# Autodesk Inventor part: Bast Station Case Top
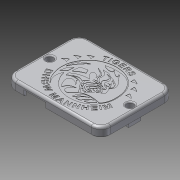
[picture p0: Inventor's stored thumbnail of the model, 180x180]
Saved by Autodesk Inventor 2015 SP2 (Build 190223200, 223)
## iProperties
Created: 2014-11
Part Number: Bast Station Case Top
Material: PC/ABS-Kunststoff
Document SubType Name: Modeling
Designer: rYan
Mass: 20.7912 g
Surface Area: 144.823 cm^2
Volume: 13.9258 cm^3
Density: 1.493 g/cm^3
Appearance: Glatt - weiß
Author: rYan
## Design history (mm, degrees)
node "Blöcke"
  sketch "Logo"
    geometry: L1 (132.873, 379.318)-(132.65, 379.619); L2 (132.65, 379.619)-(131.014, 379.945); L3 (131.014, 379.945)-(131.014, 379.945); L4 (129.973, 378.966)-(129.973, 378.966); L5 (129.973, 378.966)-(133.096, 379.016); L6 (133.096, 379.016)-(132.873, 379.318); L7 (131.014, 379.945)-(129.973, 378.966); L8 (131.956, 378.489)-(131.683, 378.414); L9 (131.683, 378.414)-(131.336, 377.836); L10 (131.336, 377.836)-(132.154, 377.736); L11 (132.154, 377.736)-(132.972, 377.635); L12 (132.972, 377.635)-(133.269, 377.309); L13 (133.269, 377.309)-(133.492, 377.409); L14 (133.492, 377.409)-(133.715, 377.51); L15 (133.715, 377.51)-(133.52, 377.541); L16 (133.52, 377.541)-(133.492, 378.112); L17 (133.492, 378.112)-(133.443, 379.117); L18 (133.443, 379.117)-(132.228, 378.564); L19 (132.228, 378.564)-(131.956, 378.489); L20 (129.066, 372.599)-(129.286, 373.295); L21 (129.286, 373.295)-(130.826, 372.487); L22 (130.826, 372.487)-(131.87, 372.626); L23 (131.87, 372.626)-(132.915, 372.766); L24 (132.915, 372.766)-(130.496, 373.657); L25 (130.496, 373.657)-(128.984, 373.295); L26 (128.984, 373.295)-(127.472, 372.933); L27 (127.472, 372.933)-(126.043, 373.378); L28 (126.043, 373.378)-(127.197, 374.994); L29 (127.197, 374.994)-(128.352, 376.609); L30 (128.352, 376.609)-(130.853, 378.28); L31 (130.853, 378.28)-(130.853, 378.28); L32 (128.819, 378.307)-(128.819, 378.307); L33 (128.819, 378.307)-(125.96, 375.857); L34 (125.96, 375.857)-(125.136, 375.634); L35 (125.136, 375.634)-(126.125, 373.796); L36 (126.125, 373.796)-(125.533, 372.884); L37 (125.533, 372.884)-(126.318, 372.487); L38 (126.318, 372.487)-(127.197, 372.042); L39 (127.197, 372.042)-(129.369, 371.039); L40 (129.369, 371.039)-(130.826, 371.234); L41 (130.826, 371.234)-(131.046, 371.624); L42 (131.046, 371.624)-(131.376, 372.097); L43 (131.376, 372.097)-(131.376, 372.097); L44 (131.376, 372.097)-(131.376, 372.097); L45 (131.376, 372.097)-(128.847, 371.902); L46 (128.847, 371.902)-(129.066, 372.599); L47 (130.853, 378.28)-(128.819, 378.307); L48 (124.888, 373.211)-(124.806, 373.657); L49 (124.806, 373.657)-(123.929, 374.483); L50 (123.929, 374.483)-(123.734, 374.186); L51 (123.734, 374.186)-(123.349, 373.601); L52 (123.349, 373.601)-(122.002, 375.105); L53 (122.002, 375.105)-(122.002, 375.105); L54 (122.002, 375.105)-(122.002, 375.105); L55 (122.002, 375.105)-(123.541, 373.072); L56 (123.541, 373.072)-(123.816, 372.766); L57 (123.816, 372.766)-(124.503, 372.738); L58 (124.503, 372.738)-(124.971, 372.766); L59 (124.971, 372.766)-(124.888, 373.211); L60 (130.228, 362.052)-(131.209, 362.075); L61 (131.209, 362.075)-(132.085, 362.167); L62 (132.085, 362.167)-(133.407, 362.421); L63 (133.407, 362.421)-(133.726, 362.482); L64 (133.726, 362.482)-(134.413, 365.932)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; 10 further points
    constraints: 358 end point, 8 point on line, 1 coincident, 835 other
  sketch "TigersLogo"
    geometry: L1 (136.84, 401.699)-(136.765, 401.634); L2 (136.951, 401.726)-(136.84, 401.699); L3 (136.765, 401.634)-(136.725, 401.531); L4 (136.725, 401.531)-(136.688, 401.438); L5 (136.688, 401.438)-(136.698, 401.342); L6 (136.698, 401.342)-(136.753, 401.244); L7 (136.753, 401.244)-(136.824, 401.119); L8 (136.824, 401.119)-(137.041, 400.933); L9 (137.041, 400.933)-(137.404, 400.686); L10 (137.404, 400.686)-(137.767, 400.439); L11 (137.767, 400.439)-(138.025, 400.23); L12 (138.025, 400.23)-(138.178, 400.057); L13 (138.178, 400.057)-(138.331, 399.885); L14 (138.331, 399.885)-(138.429, 399.693); L15 (138.429, 399.693)-(138.47, 399.481); L16 (138.47, 399.481)-(138.512, 399.269); L17 (138.512, 399.269)-(138.485, 399.038); L18 (138.485, 399.038)-(138.387, 398.787); L19 (138.387, 398.787)-(138.299, 398.561); L20 (138.299, 398.561)-(138.152, 398.374); L21 (138.152, 398.374)-(137.946, 398.226); L22 (137.946, 398.226)-(137.74, 398.078); L23 (137.74, 398.078)-(137.5, 398.002); L24 (137.5, 398.002)-(137.226, 397.998); L25 (137.226, 397.998)-(136.952, 397.994); L26 (136.952, 397.994)-(136.639, 398.06); L27 (136.639, 398.06)-(136.286, 398.197); L28 (136.286, 398.197)-(135.773, 398.397); L29 (135.773, 398.397)-(135.424, 398.666); L30 (135.424, 398.666)-(135.238, 399.004); L31 (135.238, 399.004)-(135.053, 399.342); L32 (135.053, 399.342)-(135.02, 399.743); L33 (135.02, 399.743)-(135.138, 400.206); L34 (138.922, 400.506)-(138.088, 400.79); L35 (116.631, 365.972)-(116.631, 365.972); L36 (116.631, 365.972)-(116.205, 368.113); L37 (116.205, 368.113)-(116.631, 368.745); L38 (116.631, 368.745)-(117.087, 369.423); L39 (117.087, 369.423)-(119.429, 368.776); L40 (119.429, 368.776)-(119.429, 368.776); L41 (119.429, 368.776)-(119.429, 368.776); L42 (119.429, 368.776)-(118.517, 368.591); L43 (118.517, 368.591)-(117.757, 368.036); L44 (117.757, 368.036)-(117.027, 367.504); L45 (117.027, 367.504)-(116.631, 365.972); L46 (116.631, 365.972)-(116.631, 365.972); L47 (140.827, 377.298)-(141.094, 377.264); L48 (141.094, 377.264)-(142.968, 375.535); L49 (142.968, 375.535)-(143.203, 375.162); L50 (143.203, 375.162)-(143.437, 374.789); L51 (143.437, 374.789)-(143.336, 374.586); L52 (143.336, 374.586)-(143.035, 374.958); L53 (143.035, 374.958)-(142.734, 375.331); L54 (142.734, 375.331)-(140.659, 376.993); L55 (140.659, 376.993)-(140.659, 376.993); L56 (140.659, 376.993)-(140.659, 376.993); L57 (140.659, 376.993)-(140.559, 377.332); L58 (140.559, 377.332)-(140.827, 377.298); L59 (144.039, 377.332)-(143.002, 377.365); L60 (143.002, 377.365)-(140.091, 378.281); L61 (140.091, 378.281)-(140.091, 378.281); L62 (140.091, 378.281)-(140.091, 378.281); L63 (140.091, 378.281)-(141.621, 378.209); L64 (141.621, 378.209)-(142.782, 377.954)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; 1 further point
    constraints: 358 end point, 825 other
sketch "Skizze1"
  geometry: L1 (-37, 28)-(37, 28); L2 (37, 28)-(37, -28); L3 (37, -28)-(-37, -28); L4 (-37, -28)-(-37, 28); L5 (0, 39.2)-(0, -39.2) reference; L6 (-51.8, 0)-(51.8, 0) reference; 1 further point
  constraints: 8 end point, 2 parallel, 1 horizontal, 1 perpendicular, 2 other
  dimensions: "d0" = 56 distance of L3.end L1.start; "d2" = 74 distance of L1.start L1.end
extrude "Extrusion1" new body sketch "Skizze1" distance "d3" = 5; taper "d4" = 0 deg
feature "Wandstärke1" dims "d5" = 2
fillet "Rundung1" dims "d6" = 6, "d7" = 8
sketch "Skizze2"
  geometry: L1 (39, 8.4)-(39, -1.4) reference; L2 (70, 0)-(8, 0) reference; L3 (8, 7)-(70, 7) reference; L4 (32.6, 0)-(14.6, 0); L5 (14.6, 0)-(14.6, 4); L6 (14.6, 4)-(32.6, 4); L7 (32.6, 4)-(32.6, 0); L8 (70, 7)-(70, 0) reference; L9 (8, 0)-(8, 7) reference; 1 further point
  constraints: 8 end point, 2 parallel, 1 horizontal, 1 perpendicular, 1 point on line
  dimensions: "d8" = 6.4 distance between parallel lines of L1 L7; "d9" = 18 distance of L5.end L6.end; "d10" = 4 distance of L4.end L5.end
extrude "Extrusion2" cut sketch "Skizze2" distance "d11" = 3; taper "d12" = 0 deg
sketch "Skizze3"
  geometry: L1 (8, 0)-(70, 0) reference; L2 (70, -7)-(8, -7) reference; L3 (39, 1.4)-(39, -8.4) reference; L4 (16.5, 0)-(60.5, 0); L5 (60.5, 0)-(60.5, -2); L6 (60.5, -2)-(16.5, -2); L7 (16.5, -2)-(16.5, 0); L8 (70, 0)-(70, -7) reference; L9 (8, -7)-(8, 0) reference; 1 further point
  constraints: 8 end point, 2 parallel, 1 horizontal, 1 perpendicular, 1 point on line
  dimensions: "d13" = 2 distance of L6.end L4.start; "d15" = 44 distance of L5.end L6.end; "d16" = 22.5 distance between parallel lines of L7 L3
extrude "Extrusion3" cut sketch "Skizze3" distance "d17" = 3; taper "d18" = 0 deg
feature "Lippe1" dims "d19" = 1, "d20" = 1.2, "d21" = 0, "d22" = 0, "d23" = 10 deg, "d24" = 0
sketch "Skizze4"
  geometry: L1 (6, 0)-(68, 0) reference; L2 (0, -50)-(0, -6) reference; L3 (68, -56)-(6, -56) reference; L4 (74, -6)-(74, -50) reference; L5 (74, -23)-(66, -23); L6 (66, -23)-(66, -33); L7 (66, -33)-(74, -33); L8 (74, -33)-(74, -23); L9 (0, -23)-(8, -23); L10 (8, -23)-(8, -33); L11 (8, -33)-(0, -33); L12 (0, -33)-(0, -23); L13 (-17.6, -28)-(91.6, -28) reference; L14 (37, -70)-(37, 14) reference; A1 r 6 centre (6, -50) between (0, -50) and (6, -56) reference; A2 r 6 centre (68, -50) between (68, -56) and (74, -50) reference; A3 r 6 centre (68, -6) between (74, -6) and (68, 0) reference; A4 r 6 centre (6, -6) between (6, 0) and (0, -6) reference; 1 further point
  constraints: 16 end point, 4 parallel, 2 horizontal, 2 perpendicular, 2 point on line, 4 other
  dimensions: "d25" = 10 distance of L5.end L6.end; "d27" = 8 distance of L6.end L7.end
extrude "Extrusion4" join sketch "Skizze4" distance "d28" = 10; taper "d29" = 0 deg
sketch "Skizze5"
  geometry: L1 (-37, 5)-(-29, 5) reference; L2 (-29, 5)-(-29, -5) reference; L3 (-29, -5)-(-37, -5) reference; L4 (-37, -5)-(-37, 5) reference; L5 (37, 5)-(37, -5) reference; L6 (37, -5)-(29, -5) reference; L7 (29, -5)-(29, 5) reference; L8 (29, 5)-(37, 5) reference; L9 (-33, 5)-(-33, -5); L10 (33, 5)-(33, -5); C1 r 3 at (-33, 0); C2 r 3 at (33, 0); 1 further point
  constraints: 6 midpoint, 4 end point, 2 centre point
  dimensions: "d30" = 6 diameter of C1; "d31" = 6 diameter of C2
extrude "Extrusion5" cut sketch "Skizze5" distance "d32" = 10; taper "d33" = 0 deg
sketch "Skizze6"
  geometry: C1 r 3 at (0, 0) reference; C2 r 3 at (66, 0) reference; 3 further points
  constraints: 2 coincident
hole "Bohrung1" sketch "Skizze6" at (0, 0), (66, 0) diameter "d34" = 3.2; stored, may be unused: countersink angle "d38" = 90 deg, drill point angle "d40" = 118 deg; dims "d35" = 6, "d36" = 4, "d37" = 2, "d39" = 8
fillet "Rundung2" dims "d41" = 2
feature "Flächenverjüngung1" dims angle "d42" = 5 deg
feature "Flächenverjüngung2" dims angle "d43" = 5 deg
fillet "Rundung3" dims "d44" = 1
sketch "Skizze7"
  geometry: L1 (0, 56)-(62, 56) reference; L2 (9.5, 56)-(0, 56) reference; L3 (9.5, 56)-(53.5, 56) reference; L4 (62, 56)-(53.5, 56) reference; L5 (-8, 4)-(-8, 48) reference; L6 (-8, 48)-(-8, 4) reference; L7 (11, 42)-(51, 42); L8 (51, 42)-(51, 37); L9 (51, 37)-(11, 37); L10 (11, 37)-(11, 42); L11 (31, -16)-(31, 68) reference; 1 further point
  constraints: 8 end point, 2 parallel, 1 horizontal, 1 perpendicular, 1 other
  dimensions: "d45" = 14 distance between parallel lines of L7 L1; "d46" = 40 distance of L8.end L9.end; "d47" = 5 distance of L9.end L7.start
extrude "Extrusion6" join sketch "Skizze7" distance "d48" = 3; taper "d49" = 0 deg
fillet "Rundung4" dims "d50" = 1
sketch "Skizze8"
  geometry: 1 further point
extrude "Extrusion7" cut sketch "Skizze8" distance "d51" = 0.25; taper "d52" = 0 deg
node "Volumenkörper1"
node "Projizierte Kontur1"
node "Projizierte Kontur2"
node "Projizierte Kontur3"
node "Projizierte Kontur4"
node "Projizierte Kontur5"
node "Projizierte Kontur6"
node "Projizierte Kontur7"
node "TigersLogo:1"
